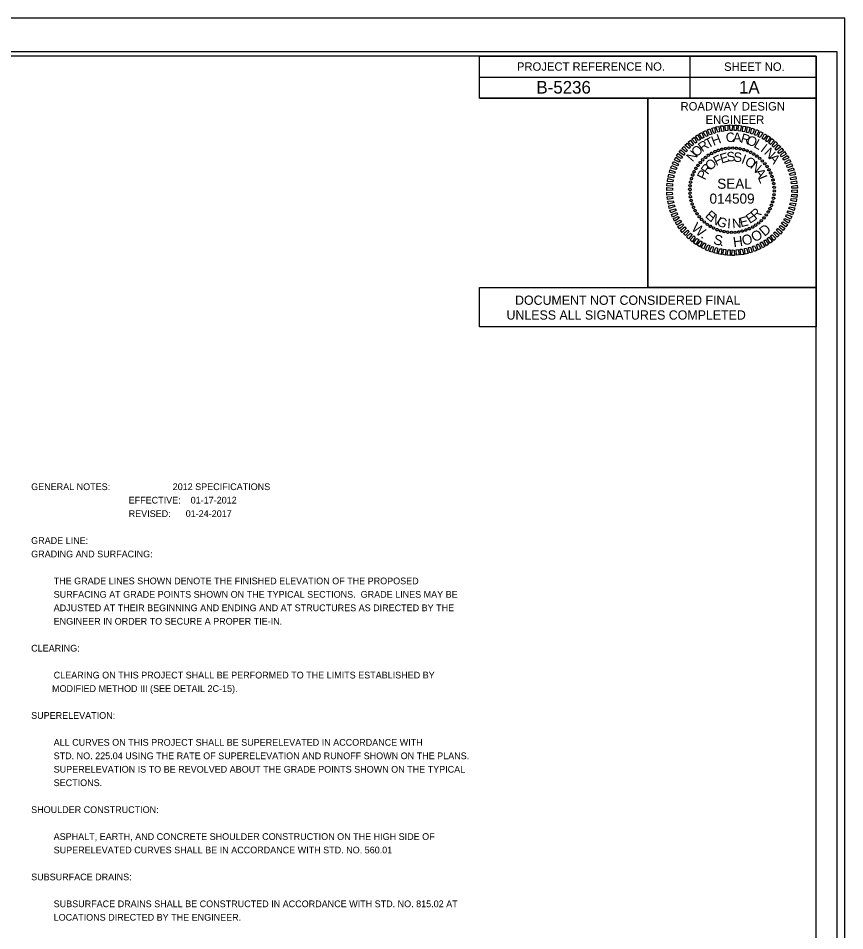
# Model space of a CAD drawing. Extents: x 9834 to 11517, y 9978 to 11072.
# Drawn here: x 11026 to 11517, y 10530 to 11072 of the extents above; entities that cross this region are included whole.
import ezdxf

# ---------------------------------------------------------------- set-up
doc = ezdxf.new("R2010")
doc.units = 0
for name, color, linetype in [('Default', 7, 'Continuous'), ('Sheet Cutting Line CELL', 7, 'Continuous'), ('Sheet Data Field CELL', 7, 'Continuous'), ('Sheet PE Seal Cell', 7, 'Continuous'), ('Sheet Plan CELL', 7, 'Continuous'), ('Sheet Plot Border Inside CELL', 7, 'Continuous'), ('Sheet Plot Border Outside CELL', 7, 'Continuous'), ('Sheet Sticker Exception Certification CELL', 7, 'Continuous'), ('Typical Detail Wedge2 CELL', 7, 'Continuous')]:
    doc.layers.add(name, color=color, linetype=linetype)

msp = doc.modelspace()

# ---------------------------------------------------------------- linework, layer by layer
at = {"layer": 'Sheet Cutting Line CELL'}
msp.add_line((11517, 11072.5), (9833.5, 11072.5), dxfattribs=at)
at = {"layer": 'Sheet PE Seal Cell'}
for p, q in [((11437.87, 10992.21), (11437.87, 10992.21)), ((11439.82, 10993.21), (11439.82, 10993.21)), ((11441.82, 10994.01), (11441.82, 10994.01)), ((11443.92, 10994.61), (11443.92, 10994.61)), ((11446.12, 10995.01), (11446.12, 10995.01)), ((11448.27, 10995.31), (11448.27, 10995.31)), ((11450.47, 10995.36), (11450.47, 10995.36)), ((11452.67, 10995.21), (11452.67, 10995.21)), ((11454.82, 10994.86), (11454.82, 10994.86)), ((11456.92, 10994.41), (11456.92, 10994.41)), ((11459.02, 10993.71), (11459.02, 10993.71)), ((11461.02, 10992.81), (11461.02, 10992.81)), ((11462.97, 10991.81), (11462.97, 10991.81)), ((11431.07, 10986.76), (11431.07, 10986.76)), ((11432.57, 10988.31), (11432.57, 10988.31)), ((11434.22, 10989.81), (11434.22, 10989.81)), ((11435.97, 10991.06), (11435.97, 10991.06)), ((11464.77, 10990.56), (11464.77, 10990.56)), ((11466.52, 10989.21), (11466.52, 10989.21)), ((11468.07, 10987.71), (11468.07, 10987.71)), ((11427.47, 10981.26), (11427.47, 10981.26)), ((11428.47, 10983.21), (11428.47, 10983.21)), ((11429.72, 10985.01), (11429.72, 10985.01)), ((11469.57, 10986.06), (11469.57, 10986.06)), ((11470.82, 10984.31), (11470.82, 10984.31)), ((11471.97, 10982.41), (11471.97, 10982.41)), ((11425.87, 10977.16), (11425.87, 10977.16)), ((11426.57, 10979.26), (11426.57, 10979.26)), ((11472.97, 10980.46), (11472.97, 10980.46)), ((11473.77, 10978.46), (11473.77, 10978.46)), ((11474.37, 10976.36), (11474.37, 10976.36)), ((11424.92, 10970.71), (11424.92, 10970.71)), ((11425.07, 10972.91), (11425.07, 10972.91)), ((11425.42, 10975.06), (11425.42, 10975.06)), ((11450.02, 10970.26), (11450.02, 10970.26)), ((11474.77, 10974.16), (11474.77, 10974.16)), ((11475.07, 10972.01), (11475.07, 10972.01)), ((11424.97, 10968.51), (11424.97, 10968.51)), ((11425.27, 10966.36), (11425.27, 10966.36)), ((11474.62, 10965.46), (11474.62, 10965.46)), ((11474.97, 10967.61), (11474.97, 10967.61)), ((11475.12, 10969.81), (11475.12, 10969.81)), ((11425.67, 10964.16), (11425.67, 10964.16)), ((11426.27, 10962.06), (11426.27, 10962.06)), ((11427.07, 10960.06), (11427.07, 10960.06)), ((11472.57, 10959.26), (11472.57, 10959.26)), ((11473.47, 10961.26), (11473.47, 10961.26)), ((11474.17, 10963.36), (11474.17, 10963.36)), ((11428.07, 10958.11), (11428.07, 10958.11)), ((11429.22, 10956.21), (11429.22, 10956.21)), ((11430.47, 10954.46), (11430.47, 10954.46)), ((11470.32, 10955.51), (11470.32, 10955.51)), ((11471.57, 10957.31), (11471.57, 10957.31)), ((11431.97, 10952.81), (11431.97, 10952.81)), ((11433.52, 10951.31), (11433.52, 10951.31)), ((11435.27, 10949.96), (11435.27, 10949.96)), ((11437.07, 10948.71), (11437.07, 10948.71)), ((11464.07, 10949.46), (11464.07, 10949.46)), ((11465.82, 10950.71), (11465.82, 10950.71)), ((11467.47, 10952.21), (11467.47, 10952.21)), ((11468.97, 10953.76), (11468.97, 10953.76)), ((11439.02, 10947.71), (11439.02, 10947.71)), ((11441.02, 10946.81), (11441.02, 10946.81)), ((11443.12, 10946.11), (11443.12, 10946.11)), ((11445.22, 10945.66), (11445.22, 10945.66)), ((11447.37, 10945.31), (11447.37, 10945.31)), ((11449.57, 10945.16), (11449.57, 10945.16)), ((11451.77, 10945.21), (11451.77, 10945.21)), ((11453.92, 10945.51), (11453.92, 10945.51)), ((11456.12, 10945.91), (11456.12, 10945.91)), ((11458.22, 10946.51), (11458.22, 10946.51)), ((11460.22, 10947.31), (11460.22, 10947.31)), ((11462.17, 10948.31), (11462.17, 10948.31))]:
    msp.add_line(p, q, dxfattribs=at)
for points in [[(11441.52, 11004.71), (11440.47, 11007.86), (11442.17, 11008.21), (11442.57, 11004.96)], [(11443.92, 11005.26), (11443.12, 11008.46), (11444.77, 11008.61), (11445.12, 11005.41)], [(11446.32, 11005.56), (11445.77, 11008.76), (11447.47, 11008.96), (11447.52, 11005.71)], [(11448.82, 11005.81), (11448.57, 11009.06), (11450.22, 11009.01), (11450.02, 11005.76)], [(11451.22, 11005.76), (11451.22, 11009.01), (11452.87, 11008.96), (11452.42, 11005.71)], [(11453.72, 11005.61), (11453.92, 11008.86), (11455.57, 11008.56), (11454.92, 11005.41)], [(11456.12, 11005.21), (11456.57, 11008.41), (11458.22, 11008.16), (11457.32, 11005.06)], [(11430.12, 10999.76), (11428.27, 11002.31), (11429.57, 11003.26), (11431.22, 11000.36)], [(11432.32, 11001.01), (11430.47, 11003.71), (11432.02, 11004.51), (11433.27, 11001.61)], [(11434.47, 11002.21), (11432.87, 11005.01), (11434.42, 11005.71), (11435.57, 11002.66)], [(11436.67, 11003.26), (11435.37, 11006.16), (11436.87, 11006.76), (11437.92, 11003.56)], [(11439.12, 11004.06), (11437.97, 11007.06), (11439.52, 11007.51), (11440.17, 11004.41)], [(11458.67, 11004.66), (11459.17, 11007.91), (11460.87, 11007.51), (11459.72, 11004.41)], [(11461.07, 11004.01), (11461.82, 11007.11), (11463.37, 11006.61), (11462.12, 11003.66)], [(11463.32, 11003.11), (11464.47, 11006.26), (11465.87, 11005.66), (11464.47, 11002.76)], [(11465.57, 11002.16), (11466.82, 11005.11), (11468.37, 11004.41), (11466.67, 11001.61)], [(11467.87, 11001.01), (11469.22, 11003.86), (11470.72, 11003.01), (11468.82, 11000.41)], [(11424.57, 10994.96), (11422.02, 10997.01), (11423.27, 10998.16), (11425.37, 10995.76)], [(11426.22, 10996.71), (11424.02, 10998.91), (11425.22, 11000.11), (11427.17, 10997.41)], [(11428.22, 10998.26), (11426.07, 11000.66), (11427.42, 11001.71), (11429.17, 10998.91)], [(11469.82, 10999.66), (11471.57, 11002.56), (11472.87, 11001.51), (11470.92, 10999.06)], [(11471.87, 10998.16), (11473.72, 11000.91), (11475.02, 10999.81), (11472.82, 10997.46)], [(11473.77, 10996.61), (11475.82, 10999.21), (11477.02, 10998.01), (11474.72, 10995.86)], [(11475.57, 10994.86), (11477.72, 10997.21), (11478.92, 10996.01), (11476.32, 10994.06)], [(11419.82, 10989.16), (11417.02, 10990.66), (11418.02, 10992.06), (11420.62, 10990.06)], [(11421.32, 10991.16), (11418.62, 10992.86), (11419.57, 10994.31), (11421.97, 10992.11)], [(11422.82, 10993.06), (11420.22, 10995.01), (11421.32, 10996.31), (11423.52, 10993.96)], [(11477.32, 10993.06), (11479.62, 10995.31), (11480.67, 10993.96), (11478.02, 10992.06)], [(11478.82, 10991.11), (11481.27, 10993.21), (11482.22, 10991.76), (11479.42, 10990.16)], [(11417.62, 10984.71), (11414.52, 10985.86), (11415.27, 10987.41), (11418.12, 10985.81)], [(11418.62, 10987.01), (11415.77, 10988.26), (11416.52, 10989.81), (11419.22, 10987.96)], [(11480.12, 10989.06), (11482.77, 10990.96), (11483.72, 10989.46), (11480.82, 10988.06)], [(11481.42, 10986.86), (11484.22, 10988.61), (11484.87, 10987.06), (11482.02, 10985.91)], [(11415.87, 10980.11), (11412.77, 10980.76), (11413.12, 10982.41), (11416.27, 10981.16)], [(11416.62, 10982.51), (11413.52, 10983.41), (11414.17, 10984.96), (11417.17, 10983.56)], [(11482.42, 10984.71), (11485.37, 10986.21), (11486.02, 10984.61), (11482.92, 10983.61)], [(11483.32, 10982.36), (11486.37, 10983.66), (11486.92, 10982.11), (11483.82, 10981.31)], [(11484.12, 10979.96), (11487.32, 10981.11), (11487.62, 10979.46), (11484.47, 10978.91)], [(11414.82, 10975.16), (11411.62, 10975.46), (11411.82, 10977.16), (11415.07, 10976.36)], [(11415.22, 10977.71), (11412.12, 10978.11), (11412.47, 10979.81), (11415.62, 10978.76)], [(11484.72, 10977.56), (11487.87, 10978.51), (11488.17, 10976.81), (11485.02, 10976.51)], [(11485.17, 10975.16), (11488.42, 10975.86), (11488.57, 10974.16), (11485.37, 10973.96)], [(11414.52, 10970.26), (11411.27, 10970.11), (11411.27, 10971.81), (11414.52, 10971.46)], [(11414.57, 10972.76), (11411.32, 10972.86), (11411.42, 10974.51), (11414.67, 10973.96)], [(11485.47, 10972.76), (11488.72, 10973.16), (11488.82, 10971.46), (11485.57, 10971.56)], [(11485.52, 10970.26), (11488.77, 10970.41), (11488.77, 10968.71), (11485.52, 10969.06)], [(11414.57, 10967.76), (11411.32, 10967.36), (11411.22, 10969.06), (11414.47, 10968.96)], [(11414.87, 10965.36), (11411.62, 10964.66), (11411.47, 10966.36), (11414.67, 10966.56)], [(11485.22, 10965.36), (11488.42, 10965.06), (11488.22, 10963.36), (11484.97, 10964.16)], [(11485.47, 10967.76), (11488.72, 10967.66), (11488.62, 10966.01), (11485.37, 10966.56)], [(11415.32, 10962.96), (11412.17, 10962.01), (11411.87, 10963.71), (11415.02, 10964.01)], [(11415.92, 10960.56), (11412.72, 10959.41), (11412.42, 10961.06), (11415.57, 10961.61)], [(11484.17, 10960.41), (11487.27, 10959.76), (11486.92, 10958.11), (11483.77, 10959.36)], [(11484.82, 10962.81), (11487.92, 10962.41), (11487.57, 10960.71), (11484.42, 10961.76)], [(11416.72, 10958.16), (11413.67, 10956.86), (11413.12, 10958.41), (11416.22, 10959.21)], [(11417.62, 10955.81), (11414.67, 10954.31), (11414.02, 10955.91), (11417.12, 10956.91)], [(11418.62, 10953.66), (11415.82, 10951.91), (11415.17, 10953.46), (11418.02, 10954.61)], [(11482.42, 10955.81), (11485.52, 10954.66), (11484.77, 10953.11), (11481.92, 10954.71)], [(11483.42, 10958.01), (11486.52, 10957.11), (11485.87, 10955.56), (11482.87, 10956.96)], [(11419.92, 10951.46), (11417.27, 10949.56), (11416.32, 10951.06), (11419.22, 10952.46)], [(11421.22, 10949.41), (11418.77, 10947.31), (11417.82, 10948.76), (11420.62, 10950.36)], [(11422.72, 10947.46), (11420.42, 10945.21), (11419.37, 10946.56), (11422.02, 10948.46)], [(11478.72, 10949.36), (11481.42, 10947.66), (11480.47, 10946.21), (11478.07, 10948.41)], [(11480.22, 10951.36), (11483.02, 10949.86), (11482.02, 10948.46), (11479.42, 10950.46)], [(11481.42, 10953.51), (11484.27, 10952.26), (11483.52, 10950.71), (11480.82, 10952.56)], [(11424.47, 10945.66), (11422.32, 10943.31), (11421.12, 10944.51), (11423.72, 10946.46)], [(11426.27, 10943.91), (11424.22, 10941.31), (11423.02, 10942.51), (11425.32, 10944.66)], [(11428.17, 10942.36), (11426.32, 10939.61), (11425.02, 10940.71), (11427.22, 10943.06)], [(11473.82, 10943.81), (11476.02, 10941.61), (11474.82, 10940.41), (11472.87, 10943.11)], [(11475.47, 10945.56), (11478.02, 10943.51), (11476.77, 10942.36), (11474.67, 10944.76)], [(11477.22, 10947.46), (11479.82, 10945.51), (11478.72, 10944.21), (11476.52, 10946.56)], [(11430.22, 10940.86), (11428.47, 10937.96), (11427.17, 10939.01), (11429.12, 10941.46)], [(11432.17, 10939.51), (11430.82, 10936.66), (11429.32, 10937.51), (11431.22, 10940.11)], [(11434.47, 10938.36), (11433.22, 10935.41), (11431.67, 10936.11), (11433.37, 10938.91)], [(11436.72, 10937.41), (11435.57, 10934.26), (11434.17, 10934.86), (11435.57, 10937.76)], [(11465.57, 10938.31), (11467.17, 10935.51), (11465.62, 10934.81), (11464.47, 10937.86)], [(11467.72, 10939.51), (11469.57, 10936.81), (11468.02, 10936.01), (11466.77, 10938.91)], [(11469.92, 10940.76), (11471.77, 10938.21), (11470.47, 10937.26), (11468.82, 10940.16)], [(11471.82, 10942.26), (11473.97, 10939.86), (11472.62, 10938.81), (11470.87, 10941.61)], [(11438.97, 10936.51), (11438.22, 10933.41), (11436.67, 10933.91), (11437.92, 10936.86)], [(11441.37, 10935.86), (11440.87, 10932.61), (11439.17, 10933.01), (11440.32, 10936.11)], [(11443.92, 10935.31), (11443.47, 10932.11), (11441.82, 10932.36), (11442.72, 10935.46)], [(11446.32, 10934.91), (11446.12, 10931.66), (11444.47, 10931.96), (11445.12, 10935.11)], [(11448.82, 10934.76), (11448.82, 10931.51), (11447.17, 10931.56), (11447.62, 10934.81)], [(11451.22, 10934.71), (11451.47, 10931.46), (11449.82, 10931.51), (11450.02, 10934.76)], [(11453.72, 10934.96), (11454.27, 10931.76), (11452.57, 10931.56), (11452.52, 10934.81)], [(11456.12, 10935.26), (11456.92, 10932.06), (11455.27, 10931.91), (11454.92, 10935.11)], [(11458.52, 10935.81), (11459.57, 10932.66), (11457.87, 10932.31), (11457.47, 10935.56)], [(11460.92, 10936.46), (11462.07, 10933.46), (11460.52, 10933.01), (11459.87, 10936.11)], [(11463.37, 10937.26), (11464.67, 10934.36), (11463.17, 10933.76), (11462.12, 10936.96)]]:
    msp.add_lwpolyline(points, close=True, dxfattribs=at)
for centre, major_axis in [((11435.99, 10991.05), (-0.403, 0.597)), ((11437.86, 10992.2), (-0.349, 0.63)), ((11439.82, 10993.17), (-0.293, 0.658)), ((11441.85, 10993.97), (-0.234, 0.681)), ((11443.95, 10994.6), (-0.174, 0.699)), ((11446.09, 10995.03), (-0.113, 0.711)), ((11448.27, 10995.28), (-0.05, 0.718)), ((11450.45, 10995.34), (0.013, 0.72)), ((11452.64, 10995.2), (0.075, 0.716)), ((11454.8, 10994.88), (0.137, 0.707)), ((11456.93, 10994.37), (0.198, 0.692)), ((11459, 10993.68), (0.258, 0.672)), ((11461.01, 10992.8), (0.316, 0.647)), ((11462.93, 10991.76), (0.371, 0.617)), ((11431.09, 10986.71), (-0.543, 0.472)), ((11432.59, 10988.3), (-0.5, 0.518)), ((11434.23, 10989.75), (-0.453, 0.56)), ((11464.76, 10990.55), (0.423, 0.582)), ((11466.47, 10989.19), (0.472, 0.543)), ((11468.06, 10987.68), (0.518, 0.5)), ((11469.51, 10986.04), (0.56, 0.453)), ((11427.47, 10981.26), (-0.647, 0.316)), ((11428.52, 10983.18), (-0.617, 0.371)), ((11429.73, 10985), (-0.582, 0.423)), ((11470.81, 10984.29), (0.597, 0.403)), ((11471.95, 10982.42), (0.63, 0.349)), ((11472.93, 10980.46), (0.658, 0.293)), ((11425.4, 10975.05), (-0.707, 0.137)), ((11425.91, 10977.17), (-0.692, 0.198)), ((11426.6, 10979.25), (-0.672, 0.258)), ((11473.73, 10978.43), (0.681, 0.234)), ((11474.35, 10976.33), (0.699, 0.174)), ((11424.94, 10970.7), (-0.72, 0.013)), ((11425.07, 10972.88), (-0.716, 0.075)), ((11474.79, 10974.18), (0.711, 0.113)), ((11475.04, 10972.01), (0.718, 0.05)), ((11475.09, 10969.82), (0.72, -0.013)), ((11425, 10968.51), (-0.718, -0.05)), ((11425.25, 10966.34), (-0.711, -0.113)), ((11425.68, 10964.19), (-0.699, -0.174)), ((11474.64, 10965.48), (0.707, -0.137)), ((11474.96, 10967.64), (0.716, -0.075)), ((11426.3, 10962.1), (-0.681, -0.234)), ((11427.1, 10960.06), (-0.658, -0.293)), ((11472.56, 10959.27), (0.647, -0.316)), ((11473.43, 10961.27), (0.672, -0.258)), ((11474.12, 10963.35), (0.692, -0.198)), ((11428.08, 10958.1), (-0.63, -0.349)), ((11429.22, 10956.24), (-0.597, -0.403)), ((11430.53, 10954.48), (-0.56, -0.453)), ((11468.94, 10953.81), (0.543, -0.472)), ((11470.31, 10955.52), (0.582, -0.423)), ((11471.51, 10957.34), (0.617, -0.371)), ((11431.98, 10952.84), (-0.518, -0.5)), ((11433.56, 10951.33), (-0.472, -0.543)), ((11435.27, 10949.97), (-0.423, -0.582)), ((11437.1, 10948.76), (-0.371, -0.617)), ((11439.02, 10947.72), (-0.316, -0.647)), ((11462.18, 10948.33), (0.349, -0.63)), ((11464.04, 10949.47), (0.403, -0.597)), ((11465.8, 10950.77), (0.453, -0.56)), ((11467.44, 10952.22), (0.5, -0.518)), ((11441.03, 10946.85), (-0.258, -0.672)), ((11443.1, 10946.15), (-0.198, -0.692)), ((11445.23, 10945.64), (-0.137, -0.707)), ((11447.39, 10945.32), (-0.075, -0.716)), ((11449.58, 10945.18), (-0.013, -0.72)), ((11451.77, 10945.24), (0.05, -0.718)), ((11453.94, 10945.49), (0.113, -0.711)), ((11456.08, 10945.93), (0.174, -0.699)), ((11458.18, 10946.55), (0.234, -0.681)), ((11460.22, 10947.35), (0.293, -0.658))]:
    msp.add_ellipse(centre, major_axis=major_axis, ratio=0.999708, dxfattribs=at)
at = {"layer": 'Sheet Plan CELL'}
for p, q in [((11425, 11049.95), (11425, 11024.95)), ((11299.95, 11037.45), (11500, 11037.45)), ((11299.95, 11024.95), (11500, 11024.95)), ((11299.95, 11024.95), (11500, 11024.95)), ((11400, 11024.95), (11400, 10912.5))]:
    msp.add_line(p, q, dxfattribs=at)
for points in [[(11500, 11050), (10000, 11050), (10000, 10000), (11500, 10000)], [(11299.95, 11050), (11500, 11050), (11500, 11024.95), (11299.95, 11024.95)], [(11400, 11024.95), (11500, 11024.95), (11500, 10912.45), (11400, 10912.45)]]:
    msp.add_lwpolyline(points, close=True, dxfattribs=at)
at = {"layer": 'Sheet Plot Border Inside CELL'}
msp.add_lwpolyline([(9846.5, 9997.5), (11512.5, 9997.5), (11512.5, 11052.5), (9846.5, 11052.5)], close=True, dxfattribs=at)
at = {"layer": 'Sheet Plot Border Outside CELL'}
msp.add_lwpolyline([(9833.5, 9977.5), (11517, 9977.5), (11517, 11072.5), (9833.5, 11072.5)], close=True, dxfattribs=at)
at = {"layer": 'Sheet Sticker Exception Certification CELL'}
for p, q in [((11299.96, 10888.96), (11299.96, 10912.46)), ((11299.96, 10912.46), (11500, 10912.46)), ((11500, 10912.45), (11500, 10888.95)), ((11500, 10888.96), (11299.96, 10888.96))]:
    msp.add_line(p, q, dxfattribs=at)

# ---------------------------------------------------------------- texts
at = {"layer": 'Default'}
for s, p in [('GENERAL NOTES:                         2012 SPECIFICATIONS', (11033.41, 10791.96)), ('                                       EFFECTIVE:    01-17-2012', (11033.41, 10783.96)), ('                                       REVISED:      01-24-2017', (11033.41, 10775.96)), ('GRADE LINE:  ', (11033.41, 10759.96)), ('GRADING AND SURFACING:  ', (11033.41, 10751.96)), ('         THE GRADE LINES SHOWN DENOTE THE FINISHED ELEVATION OF THE PROPOSED ', (11033.41, 10735.96)), ('         SURFACING AT GRADE POINTS SHOWN ON THE TYPICAL SECTIONS.  GRADE LINES MAY BE ', (11033.41, 10727.96)), ('         ADJUSTED AT THEIR BEGINNING AND ENDING AND AT STRUCTURES AS DIRECTED BY THE ', (11033.41, 10719.96)), ('         ENGINEER IN ORDER TO SECURE A PROPER TIE-IN.  ', (11033.41, 10711.96)), ('CLEARING:  ', (11033.41, 10695.96)), ('         CLEARING ON THIS PROJECT SHALL BE PERFORMED TO THE LIMITS ESTABLISHED BY ', (11033.41, 10679.96)), ('         MODIFIED METHOD III (SEE DETAIL 2C-15).', (11032.46, 10671.96)), ('SUPERELEVATION:  ', (11033.41, 10655.96)), ('         ALL CURVES ON THIS PROJECT SHALL BE SUPERELEVATED IN ACCORDANCE WITH', (11033.41, 10639.96)), ('         STD. NO. 225.04 USING THE RATE OF SUPERELEVATION AND RUNOFF SHOWN ON THE PLANS.', (11033.41, 10631.96)), ('         SUPERELEVATION IS TO BE REVOLVED ABOUT THE GRADE POINTS SHOWN ON THE TYPICAL ', (11033.41, 10623.96)), ('         SECTIONS.  ', (11033.41, 10615.96)), ('SHOULDER CONSTRUCTION:  ', (11033.41, 10599.96)), ('         ASPHALT, EARTH, AND CONCRETE SHOULDER CONSTRUCTION ON THE HIGH SIDE OF', (11033.41, 10583.96)), ('         SUPERELEVATED CURVES SHALL BE IN ACCORDANCE WITH STD. NO. 560.01', (11033.41, 10575.96)), ('SUBSURFACE DRAINS:', (11033.41, 10559.96)), ('         SUBSURFACE DRAINS SHALL BE CONSTRUCTED IN ACCORDANCE WITH STD. NO. 815.02 AT ', (11033.41, 10543.96)), ('         LOCATIONS DIRECTED BY THE ENGINEER.  ', (11033.41, 10535.96))]:
    msp.add_text(s, height=4, dxfattribs=at).set_placement(p)
at = {"layer": 'Sheet Data Field CELL'}
for s, p in [('B-5236   ', (11333.74, 11027.7)), ('1A ', (11454.11, 11027.75))]:
    msp.add_text(s, height=7.5, dxfattribs=at).set_placement(p)
at = {"layer": 'Sheet PE Seal Cell'}
for s, height, rotation, p in [('H', 5.64, 20.6195, (11438.97, 10996.61)), ('C', 5.64, 6.2199, (11446.57, 10998.61)), ('A', 5.64, 359.0203, (11450.52, 10998.91)), ('R', 5.64, 344.6211, (11454.72, 10998.71)), ('R', 5.64, 35.0205, (11432.32, 10992.76)), ('T', 5.64, 27.8198, (11435.72, 10994.96)), ('O', 5.64, 337.4212, (11458.07, 10997.96)), ('L', 5.64, 330.2209, (11462.47, 10996.11)), ('I', 5.64, 323.0201, (11466.52, 10993.71)), ('N', 5.64, 49.4235, (11426.57, 10986.76)), ('O', 5.64, 42.2217, (11428.87, 10989.66)), ('E', 5.64, 16.6111, (11443.77, 10986.06)), ('S', 5.64, 7.2556, (11447.22, 10987.11)), ('S', 5.64, 357.9004, (11450.82, 10987.16)), ('N', 5.64, 315.8189, (11468.67, 10992.16)), ('O', 5.64, 44.6812, (11437.27, 10981.61)), ('F', 5.64, 25.967, (11440.57, 10984.56)), ('I', 5.64, 339.1896, (11455.12, 10986.46)), ('O', 5.64, 329.8335, (11457.12, 10985.76)), ('N', 5.64, 320.4766, (11460.47, 10983.76)), ('A', 5.64, 308.6172, (11471.62, 10989.21)), ('P', 5.64, 63.3989, (11433.92, 10975.96)), ('R', 5.64, 54.0397, (11435.52, 10979.16)), ('A', 5.64, 301.7603, (11463.32, 10981.16)), ('SEAL', 5.998, 360, (11441.22, 10971.11)), ('L', 5.64, 292.4008, (11465.27, 10977.71)), ('R', 5.64, 42.4814, (11464.12, 10952.51)), ('E', 5.64, 318.2769, (11433.62, 10954.61)), ('N', 5.64, 327.634, (11436.62, 10951.91)), ('G', 5.64, 336.9902, (11440.42, 10949.66)), ('E', 5.64, 14.4118, (11455.27, 10948.21)), ('E', 5.64, 33.1241, (11460.57, 10950.16)), ('I', 5.64, 355.7012, (11446.97, 10947.76)), ('N', 5.64, 5.0564, (11450.32, 10947.61))]:
    msp.add_text(s, height=height, rotation=rotation, dxfattribs=at).set_placement(p)
msp.add_text('014509', height=5.998, dxfattribs=at).set_placement((11436.63, 10962.25))
at = {"layer": 'Sheet Plan CELL'}
for s, height, p in [('PROJECT REFERENCE NO.', 5.0001, (11322.15, 11041.3)), ('SHEET NO.', 5, (11445.3, 11041.2)), ('ROADWAY DESIGN', 5.0001, (11419.4, 11017.65)), ('ENGINEER', 5, (11434.25, 11009.7))]:
    msp.add_text(s, height=height, dxfattribs=at).set_placement(p)
at = {"layer": 'Sheet Sticker Exception Certification CELL'}
for s, p in [('DOCUMENT NOT CONSIDERED FINAL', (11321.03, 10902.12)), ('UNLESS ALL SIGNATURES COMPLETED', (11315.96, 10893.32))]:
    msp.add_text(s, height=5.5, dxfattribs=at).set_placement(p)
at = {"layer": 'Typical Detail Wedge2 CELL'}
for s, rotation, p in [('W', 319.62, (11425.38, 10946.98)), ('D', 41.0529, (11469.37, 10942.43)), ('S', 346.3882, (11438.5, 10938.37)), ('H', 7.9481, (11451.03, 10936.37)), ('O', 17.9321, (11456.89, 10937.06)), ('O', 29.4925, (11463.4, 10939.11)), ('.', 332.1541, (11431.02, 10942.18)), ('.', 353.7139, (11442.66, 10937.17))]:
    msp.add_text(s, height=6, rotation=rotation, dxfattribs=at).set_placement(p)

doc.saveas('drawing.dxf')
